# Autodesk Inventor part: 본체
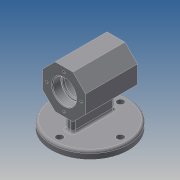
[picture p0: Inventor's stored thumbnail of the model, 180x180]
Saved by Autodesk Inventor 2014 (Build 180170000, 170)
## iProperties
Created: 2021-02
Part Number: 본체
Material: Generic
Document SubType Name: Modeling
Designer: kb542-14
Density: 1 g/cm^3
Appearance: Default
Author: kb542-14
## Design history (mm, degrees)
sketch "스케치1"
  geometry: L1 (12.012, 29)-(29, 12.012); L2 (29, 12.012)-(29, -12.012); L3 (29, -12.012)-(12.012, -29); L4 (12.012, -29)-(-12.012, -29); L5 (-12.012, -29)-(-29, -12.012); L6 (-29, -12.012)-(-29, 12.012); L7 (-29, 12.012)-(-12.012, 29); L8 (-12.012, 29)-(12.012, 29); 3 further points
  constraints: 16 end point, 1 coincident, 1 midpoint, 1 vertical alignment, 17 other
  dimensions: "d0" = 58 distance between parallel lines of L3 L7
extrude "돌출1" new body sketch "스케치1" stored distance "d1" = 70; taper "d2" = 0 deg
sketch "스케치2"
  geometry: L1 (29, -35)-(-29, -35) reference; L2 (-29, -35)-(-29, 35) reference; L3 (-29, 35)-(29, 35) reference; L4 (29, 35)-(29, -35) reference; L5 (0, 35)-(0, -35); L6 (0, -35)-(16, -35); L7 (16, -35)-(16, -23); L8 (16, -23)-(14, -23); L9 (14, -23)-(14, -20); L10 (14, -20)-(22, -20); L11 (22, -20)-(22, 20); L12 (22, 20)-(14, 20); L13 (14, 20)-(14, 23); L14 (14, 23)-(16, 23); L15 (16, 23)-(16, 35); L16 (16, 35)-(0, 35); 1 further point
  constraints: 24 end point, 6 parallel, 4 perpendicular, 2 midpoint, 2 point on line
  dimensions: "d3" = 44 diameter of L11 L5; "d4" = 32 diameter of L15 L5; "d5" = 28 diameter of L13 L5; "d6" = 28 diameter of L9 L5; "d7" = 32 diameter of L7 L5; "d8" = 40 distance of L10.end L11.end; "d9" = 12 distance of L14.end L15.end; "d10" = 3 distance of L12.end L13.end; "d11" = 3 distance of L8.end L9.end
revolve "회전1" sketch "스케치2" stored, may be unused: angle "d12" = 90 deg
node "작업 평면1"
sketch "스케치3"
  geometry: C1 r 52 at (0, 0); 1 further point
  constraints: 1 centre point, 1 coincident
  dimensions: "d14" = 104 diameter of C1
extrude "돌출2" join sketch "스케치3" distance "d15" = 10; taper "d16" = 0 deg
sketch "스케치5"
  geometry: L1 (-28, -5)-(28, -5); L2 (28, -5)-(28, 5); L3 (28, 5)-(-28, 5); L4 (-28, 5)-(-28, -5); L5 (-28, -5)-(28, 5); L6 (28, -5)-(-28, 5); C1 r 52 at (0, 0) reference
  constraints: 12 end point, 2 midpoint, 2 parallel, 1 horizontal, 1 perpendicular
  dimensions: "d17" = 10 distance of L3.end L1.start; "d18" = 56 distance of L2.end L3.end
extrude "돌출3" join sketch "스케치5" stored distance "d19" = 10; taper "d20" = 0 deg
sketch "스케치6"
  geometry: C1 r 52 at (0, 0) reference; C2 r 4.5 at (0, 41)
  constraints: 1 centre point, 1 vertical alignment
  dimensions: "d21" = 9 diameter of C2; "d22" = 41 distance of C1.centre C2.centre
extrude "돌출4" cut sketch "스케치6" distance "d23" = 10; taper "d24" = 0 deg
fillet "모깎기1" dims "d28" = 3
fillet "모깎기2" dims "d29" = 3
fillet "모깎기3" dims "d30" = 3
fillet "모깎기4" dims "d31" = 3
chamfer "모따기1" distance "d32" = 1; stored, may be unused: second distance "d33" = 2, angle "d34" = 45 deg
sketch "스케치7"
  geometry: C1 r 17 at (0, 0) reference; 1 further point
  constraints: 1 vertical alignment
  dimensions: "d35" = 23 distance of C1.centre point (0, 23)
hole "구멍1" sketch "스케치7" at (0, 23) diameter "d36" = 3.242; stored, may be unused: countersink angle "d40" = 90 deg, drill point angle "d42" = 118 deg; dims "d37" = 8, "d38" = 4, "d39" = 2, "d41" = 10
fillet "모깎기5" dims "d46" = 0.3
fillet "모깎기6" dims "d47" = 3
node "솔리드1"
pattern_circular "원형 패턴1" dims angle "d26" = 360 deg
pattern_circular "원형 패턴2" dims angle "d44" = 360 deg
mirror "대칭1"
node "절단 모서리 투영1"
other parameters: "d13" = -59.75
